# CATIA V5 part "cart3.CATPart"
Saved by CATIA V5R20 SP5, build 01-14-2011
Part number: 支撑杆
Material "Light Beige": density 7860 kg/m3, Young's modulus 2e+11 Pa, Poisson ratio 0.266
Bounding box of the stored display mesh (mm): x -35 to 317.5, y -135 to 135, z -24 to 179.312
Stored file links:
  E:\设计\180212313林恺昇\cart3.CATPart
  C:\Program Files\Dassault Systemes\B20\intel_a\startup\materials\Catalog.CATMaterial
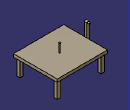
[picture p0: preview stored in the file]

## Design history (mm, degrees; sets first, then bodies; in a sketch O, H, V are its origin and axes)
Body1 (main body)
  Sketch1 on zx-plane, origin (0, 0, 0), H (-1, 0, 0), V (0, 0, 1)
    construction line L1 (0, 172) -> (0, 13.65)
    line L2 (7.5, 172) -> (7.5, 0)
    line L3 (-7.5, 0) -> (-7.5, 172)
    arc A1 centre (0, 172) radius 7.5 from (-7.5, 172) to (7.5, 172) cw
    point P4 (7.5, 0)
    point P5 (-7.5, 0)
    line L4 (-7.5, 0) -> (7.5, 0)
    distance L1 L2 = 7.5
    length L2 = 172
    distance P5 P4 = 15
    vertical: L1 V
    tangency: A1 L2, A1 L3
    horizontal: L4 H
    coincidence: L1 V, L4 H
  Pad1: profile Sketch1, direction (0, 1, 0), length 7.5, mirrored extent
  Sketch2 on end face of Pad1, origin (0, 7.5, 0), H (-1, 0, 0), V (0, 0, 1)
    circle A1 centre (0, 171) radius 4.5
    point P1 (0, 171)
    reference projected line E1 (-7.5, 0) -> (7.5, 0) from edge [face of Pad1 from Sketch1.L4 | end face of Pad1]
    radius A1 = 4.5
    distance P1 E1 = 171
    coincidence: P1 V
  Pad2: profile Sketch2, direction (0, 1, 0), length 10
  Plane1: type Offset, RefPlane xy-plane, Offset 6, reversed
  Plane2: type Offset, RefPlane Plane1, Offset 6, reversed
  Plane3: type Offset, RefPlane Plane2, Offset 6, reversed
  Plane4: type Offset, RefPlane Plane3, Offset 6, reversed
  Sketch3 on face of Pad1 from Sketch1.L4, origin (0, 0, 0), H (1, 0, 0), V (0, -1, 0)
    circle A1 centre (0, 0) radius 11
    radius A1 = 11
  Sketch4 on Plane1, origin (0, 0, -6), H (1, 0, 0), V (0, 1, 0)
    circle A1 centre (0, 0) radius 14.5
    point P1 (14.5, 0)
    radius A1 = 14.5
    coincidence: A1 P1, P1 H
  Sketch5 on Plane2, origin (0, 0, -12), H (1, 0, 0), V (0, 1, 0)
    circle A1 centre (0, 0) radius 18.5
    radius A1 = 18.5
  Sketch6 on Plane3, origin (0, 0, -18), H (1, 0, 0), V (0, 1, 0)
    circle A1 centre (0, 0) radius 25
    radius A1 = 25
  Sketch7 on Plane4, origin (0, 0, -24), H (1, 0, 0), V (0, 1, 0)
    circle A1 centre (0, 0) radius 35
    radius A1 = 35
  Loft1: solid, Sections (Sketch3; Sketch4; Sketch5; Sketch6; Sketch7)
  Fillet1: radius 5, on edge [face of Loft1 | face of Loft1]
  Body2
    Sketch8 on face of Pad1 from Sketch1.L3, origin (7.5, 0, 0), H (0, 0, 1), V (0, -1, 0)
      point P1 (85, 0)
      line L1 (94, 135) -> (94, -135)
      line L2 (94, -135) -> (76, -135)
      line L3 (76, -135) -> (76, 135)
      line L4 (76, 135) -> (94, 135)
      distance P1 V = 85
      length L2 = 18
      length L1 = 270
      coincidence: P1 H
      vertical: L1 V, L3 V
      horizontal: L2 H, L4 H
      equidistance: L1 L3 P1, L2 L4 P1
    Pad3: profile Sketch8, direction (1, 0, 0), length 310
    Sketch9 on face of Pad3 from Sketch8.L3, origin (0, 0, 76), H (1, 0, 0), V (0, -1, 0)
      point P1 (297.5, 115)
      line L1 (307.5, 125) -> (307.5, 105)
      line L2 (307.5, 105) -> (287.5, 105)
      line L3 (287.5, 105) -> (287.5, 125)
      line L4 (287.5, 125) -> (307.5, 125)
      point P2 (307.5, 125)
      point P3 (307.5, 105)
      point P4 (287.5, 105)
      point P5 (287.5, 125)
      reference projected line E1 (7.5, 135) -> (207.5, 135) from edge [face of Pad3 from Sketch8.L3 | face of Pad3 from Sketch8.L4]
      reference projected line E2 (317.5, 90) -> (317.5, -90) from edge [face of Pad3 from Sketch8.L3 | end face of Pad3]
      point P6 (307.5, -125)
      point P7 (287.5, -125)
      line L5 (287.5, -125) -> (307.5, -125)
      point P8 (287.5, -105)
      line L6 (287.5, -105) -> (287.5, -125)
      point P9 (307.5, -105)
      line L7 (307.5, -105) -> (287.5, -105)
      line L8 (307.5, -125) -> (307.5, -105)
      point P10 (297.5, -115)
      point P11 (27.5, -115)
      line L9 (37.5, -105) -> (37.5, -125)
      line L10 (37.5, -125) -> (17.5, -125)
      line L11 (17.5, -125) -> (17.5, -105)
      line L12 (17.5, -105) -> (37.5, -105)
      point P12 (37.5, -105)
      point P13 (37.5, -125)
      point P14 (17.5, -125)
      point P15 (17.5, -105)
      reference projected line E3 (7.5, -135) -> (207.5, -135) from edge [face of Pad3 from Sketch8.L2 | face of Pad3 from Sketch8.L3]
      reference projected line E4 (7.5, 90) -> (7.5, -90) from edge [start face of Pad3 | face of Pad3 from Sketch8.L3]
      point P16 (27.5, 115)
      point P17 (37.5, 105)
      point P18 (37.5, 125)
      point P19 (17.5, 125)
      point P20 (17.5, 105)
      line L13 (37.5, 105) -> (37.5, 125)
      line L14 (37.5, 125) -> (17.5, 125)
      line L15 (17.5, 125) -> (17.5, 105)
      line L16 (17.5, 105) -> (37.5, 105)
      length L4 = 20
      length L1 = 20
      distance E1 L4 = 10
      distance L1 E2 = 10
      length L10 = 20
      length L9 = 20
      distance L10 E3 = 10
      distance L11 E4 = 10
      vertical: L1 V, L3 V, L9 V, L11 V
      horizontal: L2 H, L4 H, L10 H, L12 H
      equidistance: L1 L3 P1, L2 L4 P1, L9 L11 P11, L10 L12 P11
      symmetry: P2 P6 H, P5 P7 H, L4 L5 H, P4 P8 H, L3 L6 H, P3 P9 H, L2 L7 H, L1 L8 H, P1 P10 H, P11 P16 H, P12 P17 H, P13 P18 H, P14 P19 H, P15 P20 H, L9 L13 H, L10 L14 H, L11 L15 H, L12 L16 H
    Pad4: profile Sketch9, direction (0, 0, -1), length 100
    Sketch10 on face of Pad3 from Sketch8.L1, origin (0, 0, 94), H (1, 0, 0), V (0, 1, 0)
      circle A1 centre (167.5, 0) radius 5
      point P1 (167.5, 0)
      reference projected line E1 (7.5, 135) -> (7.5, -135) from edge [start face of Pad3 | face of Pad3 from Sketch8.L1]
      radius A1 = 5
      distance P1 E1 = 160
      coincidence: P1 H
    Pad5: profile Sketch10, direction (0, 0, 1), length 50
  Assemble1: tool Body2
  Split1: SplitPlane face of Loft1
